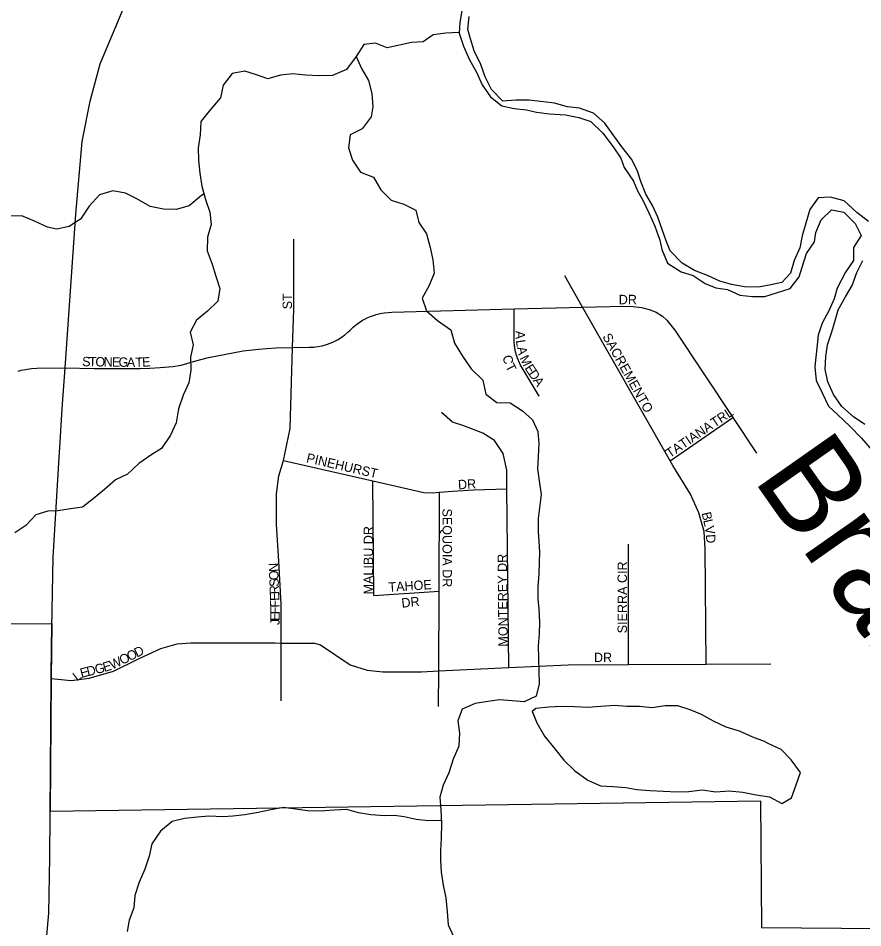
# Model space of a CAD drawing. Extents: x 1985906 to 2277390, y 930619 to 1324581.
# Drawn here: x 2143935 to 2148429, y 1150582 to 1155425 of the extents above; entities that cross this region are included whole.
import ezdxf

# ---------------------------------------------------------------- set-up
doc = ezdxf.new("R2010")
doc.units = 0
for name, color, linetype in [('GM_X_Corporation', 7, 'Continuous'), ('GM_X_Major_River', 7, 'Continuous'), ('GM_X_Major_River_Text', 7, 'Continuous'), ('GM_X_Minor_Lake', 7, 'Continuous'), ('GM_X_Minor_River', 7, 'Continuous'), ('GM_X_Township_Subdivision', 7, 'Continuous'), ('GM_X_Township_Subdivision_Text', 7, 'Continuous'), ('GM_X_US_Route', 7, 'Continuous')]:
    doc.layers.add(name, color=color, linetype=linetype)

msp = doc.modelspace()

# ---------------------------------------------------------------- linework, layer by layer
at = {"layer": 'GM_X_Corporation'}
msp.add_lwpolyline([(2141172.4, 1150523.7), (2141176.9, 1153130.2), (2142526, 1153114.4), (2142533.5, 1152195.5), (2144114.3, 1152201.6), (2144109.6, 1151909.3), (2144104.8, 1151202.7), (2147884.7, 1151258.3), (2147888.9, 1150584), (2149592.6, 1150569.7), (2149501.4, 1153117.9), (2150578.5, 1153134.9), (2150599.3, 1152254.2), (2153291.2, 1152287.9), (2153292.1, 1152173.7), (2152895.6, 1152160.7), (2152913.6, 1151526.3), (2153297.4, 1151520.3), (2153298.3, 1151420.1), (2152911.7, 1151416.2), (2152923.4, 1150801.6), (2153303.4, 1150794.8), (2153308.8, 1150124.5)], dxfattribs=at)
at = {"layer": 'GM_X_Major_River'}
for points in [[(2146295.2, 1155464.3), (2146285.2, 1155402.1), (2146281.3, 1155344), (2146303.3, 1155275.9), (2146333.4, 1155205.8), (2146373.4, 1155137.7), (2146403.5, 1155069.6), (2146447.5, 1155005.5), (2146507.5, 1154957.4), (2146573.5, 1154943.5), (2146639.5, 1154937.5), (2146691.5, 1154923.5), (2146761.5, 1154915.6), (2146847.4, 1154909.6), (2146917.4, 1154895.7), (2146981.4, 1154873.7), (2147045.4, 1154811.6), (2147099.5, 1154739.5), (2147141.5, 1154679.4), (2147159.6, 1154629.3), (2147207.6, 1154557.2), (2147229.6, 1154505.2), (2147257.7, 1154455.1), (2147289.7, 1154389), (2147321.8, 1154316.8), (2147347.8, 1154242.7), (2147359.9, 1154192.6), (2147389.9, 1154120.5), (2147461.9, 1154074.5), (2147525.9, 1154054.5), (2147589.9, 1154012.5), (2147645.9, 1153988.5), (2147707.9, 1153980.5), (2147773.9, 1153950.5), (2147841.9, 1153942.6), (2147907.9, 1153942.6), (2147973.8, 1153964.7), (2148041.8, 1153984.8), (2148089.7, 1154047), (2148105.6, 1154099.1), (2148129.6, 1154171.3), (2148171.5, 1154233.4), (2148179.4, 1154283.6), (2148207.4, 1154351.7), (2148261.3, 1154403.9), (2148327.3, 1154391.9), (2148387.3, 1154331.8), (2148419.4, 1154267.7), (2148379.4, 1154203.6), (2148379.5, 1154135.4), (2148335.6, 1154073.3), (2148291.7, 1153987.1), (2148275.7, 1153930.9), (2148247.8, 1153866.8), (2148211.9, 1153800.6), (2148191.9, 1153736.4), (2148186, 1153686.3), (2148178, 1153620.2), (2148174.1, 1153568.1), (2148180.1, 1153495.9), (2148212.2, 1153429.8), (2148246.2, 1153359.7), (2148296.2, 1153313.6), (2148360.3, 1153253.6)], [(2148459.3, 1154341.9), (2148397.3, 1154390), (2148329.2, 1154452.1), (2148257.2, 1154472), (2148191.3, 1154467.9), (2148147.3, 1154405.8), (2148125.4, 1154333.6), (2148105.5, 1154265.5), (2148093.5, 1154201.3), (2148063.6, 1154135.1), (2148043.7, 1154067), (2147997.7, 1154016.8), (2147939.8, 1154004.8), (2147873.8, 1153992.7), (2147799.9, 1153994.6), (2147729.9, 1154006.6), (2147667.9, 1154024.6), (2147601.9, 1154054.6), (2147533.9, 1154080.6), (2147467.9, 1154120.6), (2147403.8, 1154186.7), (2147381.8, 1154238.7), (2147361.8, 1154298.8), (2147337.7, 1154365), (2147309.7, 1154427.1), (2147273.6, 1154487.2), (2147247.6, 1154555.3), (2147229.6, 1154609.4), (2147199.5, 1154671.5), (2147145.5, 1154739.6), (2147099.4, 1154803.6), (2147055.4, 1154865.8), (2146995.4, 1154919.8), (2146921.4, 1154945.8), (2146857.4, 1154951.8), (2146787.4, 1154971.7), (2146729.4, 1154979.7), (2146653.5, 1154987.6), (2146581.5, 1154987.6), (2146513.5, 1154983.5), (2146453.5, 1155045.6), (2146419.4, 1155111.7), (2146395.4, 1155177.8), (2146361.3, 1155249.9), (2146341.3, 1155314), (2146327.2, 1155364.1), (2146333.2, 1155434.3)], [(2148440.2, 1153261.7), (2148378.2, 1153301.7), (2148316.2, 1153357.8), (2148272.2, 1153421.8), (2148242.1, 1153488), (2148228.1, 1153554.1), (2148232, 1153624.2), (2148239.9, 1153686.4), (2148263.9, 1153754.5), (2148283.8, 1153820.7), (2148297.7, 1153872.8), (2148335.7, 1153941), (2148371.6, 1154001.1), (2148397.5, 1154071.3), (2148429.5, 1154135.5)], [(2148360.3, 1153253.6), (2148422.3, 1153189.5), (2148478.3, 1153123.4)]]:
    msp.add_lwpolyline(points, dxfattribs=at)
at = {"layer": 'GM_X_Minor_Lake'}
for points in [[(2147925.7, 1151563.3), (2147905.7, 1151573.3), (2147843.8, 1151597.3), (2147771.9, 1151629.3), (2147702, 1151651.3), (2147634.1, 1151683.3), (2147570.1, 1151717.4), (2147510.2, 1151743.4), (2147444.3, 1151763.4), (2147376.4, 1151763.4), (2147306.5, 1151753.3), (2147240.5, 1151761.3), (2147172.6, 1151761.3), (2147106.7, 1151765.2), (2147034.8, 1151761.2), (2146964.9, 1151755.1), (2146897, 1151759.1), (2146825.1, 1151761.1), (2146757.2, 1151757), (2146689.3, 1151749), (2146669.7, 1151733.3)], [(2147925.7, 1151563.3), (2147905.7, 1151573.3), (2147843.8, 1151597.3), (2147771.9, 1151629.3), (2147702, 1151651.3), (2147634.1, 1151683.3), (2147570.1, 1151717.4), (2147510.2, 1151743.4), (2147444.3, 1151763.4), (2147376.4, 1151763.4), (2147306.5, 1151753.3), (2147240.5, 1151761.3), (2147172.6, 1151761.3), (2147106.7, 1151765.2), (2147034.8, 1151761.2), (2146964.9, 1151755.1), (2146897, 1151759.1), (2146825.1, 1151761.1), (2146757.2, 1151757), (2146689.3, 1151749), (2146669.9, 1151733.4)], [(2146669.3, 1151735), (2146693.3, 1151672.9), (2146735.3, 1151602.8), (2146789.2, 1151534.7), (2146837.2, 1151474.6), (2146897.1, 1151418.5), (2146965.1, 1151368.5), (2147033, 1151338.4), (2147100.9, 1151334.5), (2147166.8, 1151328.5), (2147226.7, 1151318.5), (2147294.6, 1151312.5), (2147368.5, 1151310.6), (2147440.5, 1151306.6), (2147502.4, 1151308.6), (2147574.3, 1151316.7), (2147646.2, 1151306.7), (2147718.1, 1151310.8), (2147790, 1151304.8), (2147861.9, 1151290.8), (2147931.8, 1151278.8), (2147997.7, 1151244.8), (2148049.7, 1151274.8), (2148073.6, 1151343), (2148097.5, 1151409.1), (2148047.6, 1151477.2), (2147993.6, 1151531.3), (2147925.7, 1151563.3)], [(2146669.9, 1151733.4), (2146693.3, 1151672.9), (2146735.3, 1151602.8), (2146789.2, 1151534.7), (2146837.2, 1151474.6), (2146897.1, 1151418.5), (2146965.1, 1151368.5), (2147033, 1151338.4), (2147100.9, 1151334.5), (2147166.8, 1151328.5), (2147226.7, 1151318.5), (2147294.6, 1151312.5), (2147368.5, 1151310.6), (2147440.5, 1151306.6), (2147502.4, 1151308.6), (2147574.3, 1151316.7), (2147646.2, 1151306.7), (2147718.1, 1151310.8), (2147790, 1151304.8), (2147861.9, 1151290.8), (2147931.8, 1151278.8), (2147997.7, 1151244.8), (2148049.7, 1151274.8), (2148073.6, 1151343), (2148097.5, 1151409.1), (2148047.6, 1151477.2), (2147993.6, 1151531.3), (2147925.7, 1151563.3)]]:
    msp.add_lwpolyline(points, dxfattribs=at)
at = {"layer": 'GM_X_Minor_River'}
for points in [[(2146281.4, 1155347.6), (2146209.6, 1155344.2), (2146141.9, 1155336.6), (2146088.9, 1155299.3), (2146027, 1155295.9), (2145897.9, 1155266.9), (2145835.4, 1155291.5), (2145773.7, 1155284.1), (2145733.2, 1155221), (2145680.9, 1155151.7), (2145607.7, 1155119.9), (2145535.9, 1155118.3), (2145464, 1155120.6), (2145395.9, 1155129), (2145330.1, 1155121.5), (2145262.7, 1155101.9), (2145202.3, 1155122.6), (2145139.9, 1155143.2), (2145072.3, 1155129.6), (2145025.8, 1155068.4), (2145011.4, 1154999.9), (2144956.9, 1154938.6), (2144906.5, 1154875.3), (2144902.1, 1154803.1), (2144891.7, 1154734.7), (2144893.3, 1154666.6), (2144900.9, 1154598.7), (2144912.4, 1154530.8), (2144932, 1154459.1), (2144953.5, 1154391.5), (2144961, 1154325.6), (2144942.6, 1154259), (2144940.3, 1154186.8), (2144965.9, 1154115.3), (2144985.3, 1154051.6), (2145006.8, 1153986), (2144996.4, 1153917.6), (2144941.7, 1153864.2), (2144882.9, 1153816.8), (2144850.4, 1153753.9), (2144865.9, 1153686.2), (2144851.5, 1153619.7), (2144853, 1153551.6), (2144842.6, 1153483.3), (2144812.2, 1153418.4), (2144787.9, 1153345.7), (2144775.6, 1153271.3), (2144745.2, 1153204.5), (2144696.9, 1153133.2), (2144639.8, 1153097.9), (2144576.9, 1153054.3), (2144516.3, 1152996.8), (2144453.1, 1152967.3), (2144394.4, 1152915.9), (2144333.6, 1152866.4), (2144276.8, 1152821), (2144213, 1152813.5), (2144145.4, 1152801.9), (2144091.5, 1152800.7), (2144028.1, 1152781.2), (2143975.5, 1152723.8), (2143916.5, 1152684.4)], [(2145733.2, 1155221), (2145760.6, 1155157.5), (2145798.1, 1155092.3), (2145815.6, 1155024.5), (2145821.3, 1154952.6), (2145812.5, 1154900.2), (2145764.1, 1154835), (2145700.9, 1154803.5), (2145692.5, 1154735.2), (2145714, 1154669.6), (2145755.4, 1154604.4), (2145825.9, 1154578), (2145863.4, 1154510.7), (2145918.6, 1154455.9), (2145986.9, 1154435.4), (2146049.6, 1154402.8), (2146067.1, 1154337.1), (2146106.4, 1154275.9), (2146126, 1154204.2), (2146141.5, 1154138.4), (2146147.2, 1154066.4), (2146120.7, 1154001.7), (2146084.3, 1153934.8), (2146107.8, 1153867.2), (2146164.9, 1153814.4), (2146236, 1153765.9), (2146255.6, 1153694.3), (2146299.1, 1153625.1), (2146344.6, 1153558.1), (2146405.9, 1153497.4), (2146423.5, 1153423.6), (2146480.5, 1153378.9), (2146552.4, 1153376.5), (2146617.3, 1153333.9), (2146670.3, 1153287.1), (2146699.7, 1153223.6), (2146705.2, 1153159.7), (2146700.8, 1153091.4), (2146698.3, 1153025.2), (2146705.8, 1152961.3), (2146717.4, 1152889.4), (2146700.4, 1152760.8), (2146701.9, 1152692.7), (2146705.1, 1152640.7), (2146708.5, 1152580.7), (2146705.7, 1152530.5), (2146705.1, 1152466.4), (2146698.7, 1152398.1), (2146700.3, 1152332), (2146705.4, 1152280), (2146709.1, 1152208), (2146706.5, 1152147.8), (2146702, 1152083.6), (2146706.6, 1151881.3), (2146690.2, 1151814.8), (2146626.9, 1151785.3), (2146562.9, 1151789.8), (2146494.9, 1151796.3), (2146433.2, 1151786.8), (2146365.5, 1151777.3), (2146296.4, 1151745.6), (2146273.8, 1151685), (2146283.3, 1151619.1), (2146278.9, 1151548.8), (2146248.6, 1151480), (2146226.3, 1151407.3), (2146195.8, 1151342.5), (2146177.3, 1151278), (2146182.9, 1151210), (2146186.5, 1151139.9), (2146184.4, 1151057.7), (2146181.9, 1150993.6), (2146181.1, 1150941.4), (2146184.5, 1150879.4), (2146196.1, 1150809.5), (2146209.6, 1150741.7), (2146217.3, 1150667.8), (2146222.9, 1150597.8), (2146252.4, 1150532.3)], [(2144923.5, 1154488.8), (2144909.6, 1154480.6), (2144844.9, 1154425.1), (2144775.5, 1154405.4), (2144707.5, 1154407.8), (2144637.3, 1154422.2), (2144566.5, 1154462.7), (2144505.9, 1154493.3), (2144437.7, 1154505.8), (2144366.3, 1154484.1), (2144311.8, 1154424.7), (2144265.4, 1154355.5), (2144206.4, 1154316.1), (2144140.9, 1154300.6), (2144090.7, 1154311.4), (2144022.1, 1154343.9), (2143953.5, 1154372.4), (2143887.7, 1154370.8)], [(2146185.6, 1151153.9), (2146182.2, 1151153.9), (2146118.3, 1151152.4), (2146052.3, 1151158.9), (2145988, 1151173.4), (2145936, 1151180.2), (2145884.1, 1151179), (2145810.1, 1151183.3), (2145745.9, 1151193.9), (2145683.6, 1151212.5), (2145615.8, 1151208.9), (2145542, 1151203.2), (2145474.1, 1151205.6), (2145345.9, 1151222.7), (2145278.3, 1151211.1), (2145210.7, 1151195.5), (2145141.1, 1151183.9), (2145077.4, 1151176.4), (2145025.5, 1151173.2), (2144949.6, 1151177.4), (2144887.8, 1151172), (2144820.1, 1151164.4), (2144754.5, 1151148.9), (2144691.8, 1151097.3), (2144645.4, 1151030.2), (2144631, 1150963.7), (2144608.6, 1150895.1), (2144578.2, 1150826.2), (2144555.9, 1150753.6), (2144549.4, 1150689.3), (2144525, 1150622.6), (2144514.4, 1150562.3)]]:
    msp.add_lwpolyline(points, dxfattribs=at)
at = {"layer": 'GM_X_Township_Subdivision'}
for points in [[(2145333.9, 1151790.3), (2145333, 1152098.5), (2145333.2, 1152305.3), (2145321.1, 1152533.6), (2145309.3, 1152729.8), (2145309.8, 1152892.1), (2145320.9, 1152988.4), (2145346.5, 1153069.6), (2145381.7, 1153240.2), (2145394.7, 1153670.9), (2145400.8, 1153874.6), (2145400.9, 1154248.5)], [(2147595.9, 1151985.2), (2147589.2, 1152599.9), (2147584.9, 1152692), (2147556.5, 1152792), (2147512.2, 1152890), (2147417.7, 1153043.9), (2147404.2, 1153067.5), (2146937.7, 1153886.2), (2146843.1, 1154052.3)], [(2145484.1, 1153672.9), (2145507.6, 1153673.8), (2145529, 1153676.3), (2145552.3, 1153680.8), (2145580.3, 1153688.8), (2145607.8, 1153699.7), (2145633.1, 1153712.5), (2145653.4, 1153725.1), (2145671.9, 1153738.7), (2145688.9, 1153753.2), (2145700, 1153764), (2145707.4, 1153771.3), (2145717.1, 1153780.2), (2145728.7, 1153789.9), (2145741, 1153799.2), (2145754.2, 1153808.2), (2145767.1, 1153816.2), (2145779.3, 1153822.9), (2145790.9, 1153828.6), (2145800, 1153832.8), (2145808.9, 1153836.5), (2145824.7, 1153842.3), (2145839.7, 1153847), (2145861.1, 1153852.3), (2145882.1, 1153856), (2145903.3, 1153858.2), (2145922.7, 1153859), (2146573.1, 1153876.5), (2146794, 1153882.4), (2146795.1, 1153882.4)], [(2146705.7, 1153412.2), (2146615.4, 1153562.6), (2146610.2, 1153571.7), (2146604.9, 1153581.7), (2146601, 1153589.8), (2146595.9, 1153601.5), (2146590.9, 1153614.3), (2146585.7, 1153630.3), (2146580.9, 1153648.2), (2146577.1, 1153667.1), (2146574.9, 1153683.5), (2146573.4, 1153702.2), (2146573.1, 1153716.4), (2146573.1, 1153876.5)], [(2146795.1, 1153882.4), (2146937.7, 1153886.2), (2147156.7, 1153892.1), (2147207.3, 1153890.2), (2147250.6, 1153884.5), (2147291.5, 1153873.7), (2147328.4, 1153858.8), (2147362.2, 1153837.5), (2147386.5, 1153817), (2147428.6, 1153763.1), (2147736.5, 1153299.5), (2147862.4, 1153109.9)], [(2144183.7, 1153563.4), (2144338.1, 1153558.9), (2144584.3, 1153558.9), (2144634.5, 1153560.9), (2144690.8, 1153564.6), (2144756.5, 1153570.8), (2144802, 1153577.8), (2144880.1, 1153601.4), (2144946.4, 1153618), (2145038.7, 1153636.9), (2145131, 1153653.4), (2145213.9, 1153662.9), (2145257.6, 1153666.7), (2145305.7, 1153669), (2145394.7, 1153670.9), (2145482.8, 1153672.8), (2145484.1, 1153672.9)], [(2143933.9, 1153546.4), (2143950, 1153550.5), (2143972.7, 1153555.1), (2144005.1, 1153559.3), (2144033.7, 1153560.8), (2144183.7, 1153563.4)], [(2146544.8, 1151968.5), (2146535.3, 1152918.9), (2146534.3, 1153019.1), (2146515.4, 1153107.1), (2146468.7, 1153176.9), (2146406.3, 1153216.3), (2146305.9, 1153255.4), (2146245.7, 1153274.8), (2146187.2, 1153326.4)], [(2147404.2, 1153067.5), (2147736.5, 1153299.5)], [(2145346.5, 1153069.6), (2145821.3, 1152962), (2146093.4, 1152900.3), (2146139.4, 1152898.7), (2146176.8, 1152901.3), (2146245.4, 1152905.9), (2146357.3, 1152913), (2146535.3, 1152918.9)], [(2145826.8, 1152352.1), (2145821.3, 1152962)], [(2146170.7, 1151760.1), (2146171.8, 1151950.1), (2146174, 1152373.7), (2146176.8, 1152901.3)], [(2147182.7, 1151983.3), (2147182.4, 1152624.7)], [(2145826.8, 1152352.1), (2146174, 1152373.7)], [(2144109.6, 1151909.3), (2144217, 1151898.4), (2144312.9, 1151911.4), (2144442.5, 1151948.8), (2144573.9, 1152014.4), (2144693.3, 1152069.7), (2144781.1, 1152094.7), (2144853.1, 1152099.5), (2145302.5, 1152098.6)], [(2145302.5, 1152098.6), (2145302.6, 1152098.6), (2145333, 1152098.5), (2145511.3, 1152098.2), (2145543.3, 1152088.5), (2145700.4, 1151981.8), (2145790.8, 1151954.7), (2145874.8, 1151945.5), (2146080.9, 1151945.7), (2146171.8, 1151950.1), (2146544.8, 1151968.5), (2146860.7, 1151981.8), (2147182.7, 1151983.3), (2147595.9, 1151985.2), (2147938.8, 1151986.8)]]:
    msp.add_lwpolyline(points, dxfattribs=at)
at = {"layer": 'GM_X_US_Route'}
for points in [[(2144155.8, 1153139.6), (2144168.4, 1153344.8), (2144183.7, 1153563.4), (2144241, 1154381.4), (2144275.2, 1154768.3), (2144317.4, 1154982.8), (2144371.5, 1155181.3), (2144487.7, 1155459.9), (2144573.8, 1155674.4)], [(2144152.6, 1153086.8), (2144155.8, 1153139.5), (2144155.8, 1153139.6)], [(2144112.4, 1152083.4), (2144112.4, 1152083.9), (2144120, 1152554.9), (2144152.6, 1153086.8), (2144152.6, 1153086.8)], [(2144104.6, 1151184.7), (2144104.6, 1151186), (2144109.6, 1151909.3), (2144112.4, 1152083.4)], [(2144021.8, 1149866.6), (2144049.6, 1150149.8), (2144068.7, 1150343.4), (2144096.9, 1150660.2), (2144103.1, 1150959), (2144104.6, 1151184.7)]]:
    msp.add_lwpolyline(points, dxfattribs=at)

# ---------------------------------------------------------------- texts
at = {"layer": 'GM_X_Major_River_Text'}
msp.add_text('Branch', height=500.26, rotation=305.0461, dxfattribs=at).set_placement((2147839.3, 1152973.8))
at = {"layer": 'GM_X_Township_Subdivision_Text'}
for s, rotation, p in [('ST', 90, (2145391.5, 1153874.9)), ('DR', 0, (2147130.1, 1153901.9)), ('A', 271.1803, (2146580.7, 1153760.2)), ('SACREMENTO', 299.2919, (2147041.5, 1153729.9)), ('L', 278.5895, (2146582.2, 1153709.2)), ('C', 280.4048, (2146512.5, 1153626.1)), ('A', 281.8279, (2146588, 1153671.3)), ('M', 295.4459, (2146601.1, 1153616)), ('S', 359.2077, (2144274.6, 1153571.9)), ('T', 359.1911, (2144309.8, 1153571.4)), ('O', 359.1912, (2144345, 1153570.9)), ('N', 359.2045, (2144389, 1153570.3)), ('E', 359.2077, (2144433, 1153569.7)), ('G', 359.1912, (2144468.2, 1153569.2)), ('A', 359.1934, (2144512.2, 1153568.6)), ('T', 0.8865, (2144557.8, 1153568)), ('E', 3.3921, (2144595.4, 1153568.6)), ('T', 297.8241, (2146525, 1153571.5)), ('E', 303.1605, (2146627.4, 1153561.9)), ('D', 303.6178, (2146646.9, 1153532.1)), ('A', 303.6832, (2146671.3, 1153495.4)), ('TRL', 33.6901, (2147639.8, 1153244.5)), ('TATIANA', 34.4614, (2147402.1, 1153081.7)), ('PINEHURST', 347.0606, (2145464.6, 1153061.3)), ('DR', 3.1785, (2146276, 1152916.3)), ('SEQUOIA DR', 270, (2146192.2, 1152814.5)), ('B', 282.6579, (2147570.4, 1152790.2)), ('L', 282.6718, (2147579.1, 1152751.5)), ('MALIBU DR', 90, (2145822.6, 1152356.9)), ('V', 279.0204, (2147586.7, 1152718)), ('D', 273.849, (2147593.4, 1152675.7)), ('MONTEREY DR', 90.5726, (2146539.9, 1152079.6)), ('N', 92.2474, (2145318.6, 1152477.7)), ('SIERRA CIR', 90, (2147173.5, 1152150.1)), ('O', 92.2474, (2145320.4, 1152433.8)), ('S', 92.2404, (2145321.8, 1152398.6)), ('TAHOE', 3.6502, (2145906.3, 1152370.7)), ('R', 92.2616, (2145323.3, 1152359)), ('E', 92.1903, (2145324.7, 1152323.7)), ('F', 91.1878, (2145325.4, 1152287.6)), ('DR', 6.0054, (2145976.4, 1152286)), ('F', 90.0273, (2145325.4, 1152251.3)), ('E', 90.0273, (2145325.5, 1152216.1)), ('J', 90.0437, (2145325.5, 1152194.1)), ('D', 26.5553, (2144566.6, 1152020.6)), ('O', 26.6002, (2144487.9, 1151981.3)), ('O', 26.5553, (2144527.2, 1152001)), ('DR', 0, (2146998.1, 1151996.7)), ('G', 15.4364, (2144349.7, 1151932.2)), ('E', 16.3658, (2144392.9, 1151944.1)), ('W', 24.3964, (2144433.9, 1151956.7)), ('L', 37.0721, (2144247.9, 1151893.1)), ('E', 15.6864, (2144271.6, 1151912.2)), ('D', 13.3419, (2144304.9, 1151921.5))]:
    msp.add_text(s, height=50, rotation=rotation, dxfattribs=at).set_placement(p)

doc.saveas('drawing.dxf')
